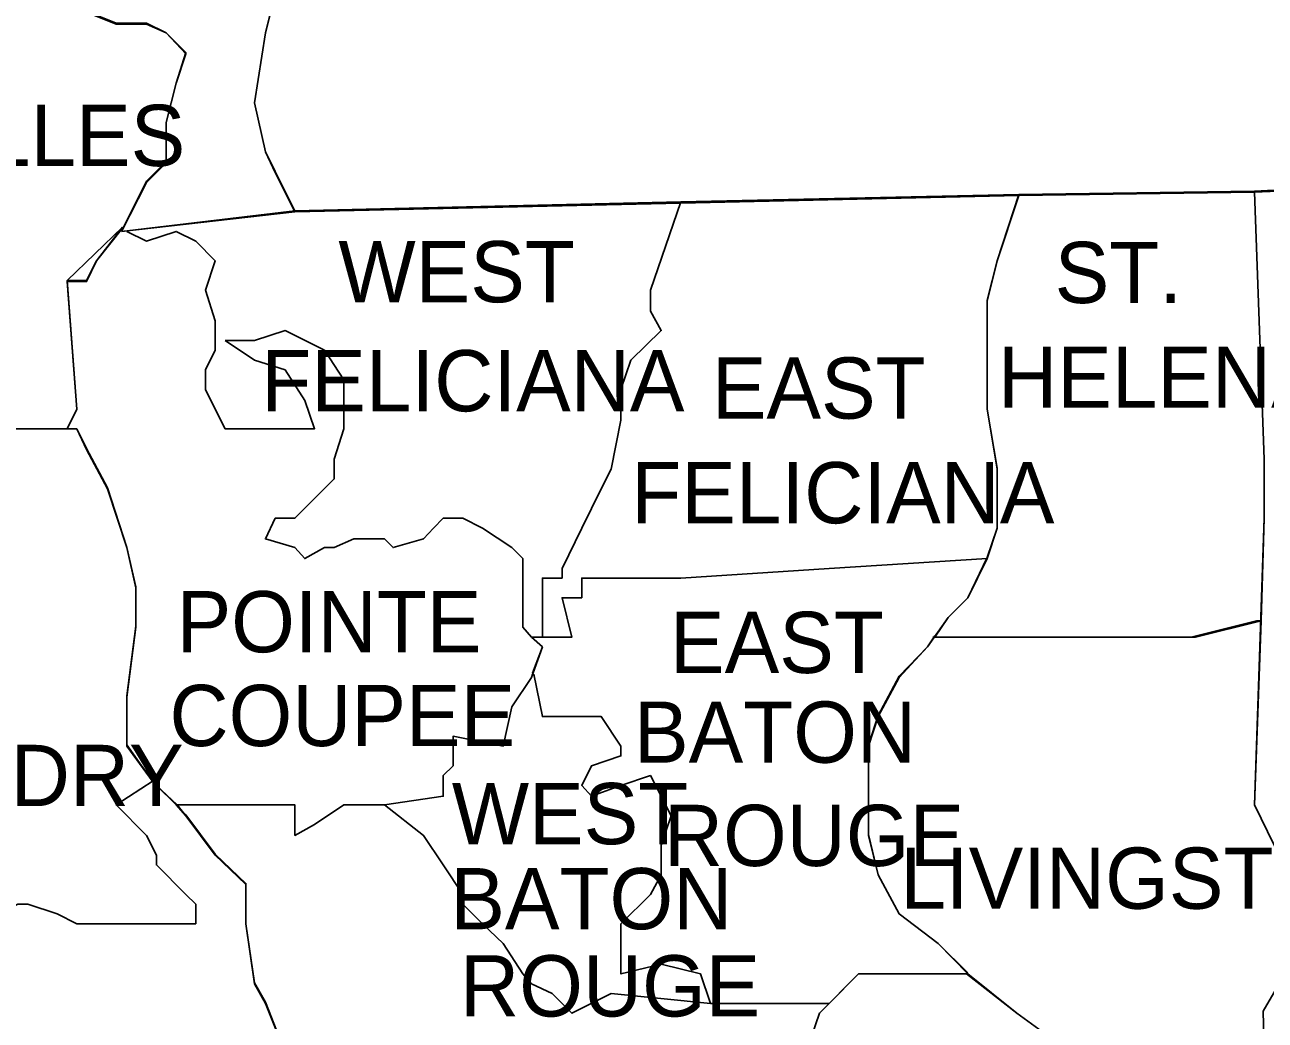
# Model space of a CAD drawing. Extents: x 0.23 to 2.82, y 0.04 to 1.79.
# Drawn here: x 2.3732 to 2.468, y 1.5179 to 1.594 of the extents above; entities that cross this region are included whole.
import ezdxf

# ---------------------------------------------------------------- set-up
doc = ezdxf.new("R2010")
doc.units = 0
for name, color, linetype in [('Dist03', 7, 'Continuous'), ('Dist08', 7, 'Continuous'), ('Dist58', 7, 'Continuous'), ('Dist61', 7, 'Continuous'), ('Dist62', 7, 'Continuous'), ('Standard Info', 7, 'Continuous')]:
    doc.layers.add(name, color=color, linetype=linetype)

msp = doc.modelspace()

# ---------------------------------------------------------------- linework, layer by layer
at = {"layer": 'Dist03'}
for points in [[(2.377154, 1.563083), (2.346904, 1.563083)], [(2.382904, 1.536167), (2.380987, 1.538917), (2.380987, 1.542667), (2.381654, 1.548), (2.381654, 1.551), (2.380987, 1.554), (2.379487, 1.558583), (2.377904, 1.561583), (2.377154, 1.563083)], [(2.409737, 1.49725), (2.408904, 1.499583), (2.407404, 1.501083), (2.403654, 1.501083), (2.402904, 1.502583), (2.402154, 1.505583), (2.40132, 1.508667), (2.40132, 1.510167), (2.400654, 1.511667), (2.39832, 1.512417), (2.39607, 1.512417), (2.39457, 1.513167), (2.39307, 1.515417), (2.39157, 1.51925), (2.390737, 1.52075), (2.39007, 1.52525), (2.39007, 1.528333), (2.387737, 1.530583), (2.385487, 1.533583), (2.384737, 1.534333)]]:
    msp.add_lwpolyline(points, dxfattribs=at)
at = {"layer": 'Dist08'}
for points in [[(2.38057, 1.578167), (2.382487, 1.582), (2.383987, 1.5835), (2.383987, 1.5865), (2.384737, 1.5895), (2.385487, 1.591833), (2.383987, 1.593333), (2.382487, 1.594083), (2.380154, 1.594083), (2.376404, 1.595583), (2.374154, 1.597833), (2.373487, 1.59875)], [(2.376404, 1.574417), (2.377904, 1.574417), (2.378654, 1.575917), (2.380654, 1.5785)], [(2.376404, 1.563083), (2.377154, 1.564583), (2.376404, 1.574417)], [(2.342404, 1.572917), (2.342404, 1.570667), (2.343904, 1.569167), (2.345404, 1.567583), (2.345404, 1.563083), (2.376404, 1.563083)]]:
    msp.add_lwpolyline(points, dxfattribs=at)
at = {"layer": 'Dist58'}
for points in [[(2.40882, 1.639417), (2.406654, 1.635667), (2.405154, 1.631917), (2.405154, 1.628083), (2.402154, 1.625083), (2.39982, 1.620583), (2.39982, 1.613), (2.39907, 1.61), (2.39757, 1.606917), (2.39682, 1.604667), (2.39457, 1.600917), (2.39307, 1.599417), (2.39157, 1.593333), (2.390737, 1.588), (2.39157, 1.58425), (2.39232, 1.58275), (2.39382, 1.57975)], [(2.38057, 1.578167), (2.382487, 1.582), (2.383987, 1.5835), (2.383987, 1.5865), (2.384737, 1.5895), (2.385487, 1.591833), (2.383987, 1.593333), (2.382487, 1.594083), (2.380154, 1.594083), (2.376404, 1.595583), (2.374154, 1.597833), (2.373487, 1.59875)], [(2.39382, 1.57975), (2.38057, 1.578167)]]:
    msp.add_lwpolyline(points, dxfattribs=at)
at = {"layer": 'Dist61'}
msp.add_line((2.376404, 1.574417), (2.380654, 1.5785), dxfattribs=at)
for points in [[(2.42332, 1.580417), (2.39382, 1.57975)], [(2.449154, 1.581), (2.42332, 1.580417)], [(2.446737, 1.55325), (2.447487, 1.5555), (2.447487, 1.560083), (2.446737, 1.564583), (2.446737, 1.569833), (2.446737, 1.572917), (2.447487, 1.575917), (2.449154, 1.581)], [(2.39382, 1.57975), (2.38057, 1.578167)], [(2.380654, 1.5785), (2.378654, 1.575917), (2.377904, 1.574417), (2.376404, 1.574417)], [(2.380487, 1.57825), (2.378654, 1.575917), (2.377904, 1.574417), (2.376404, 1.574417)], [(2.376404, 1.574417), (2.377154, 1.564583), (2.376404, 1.563083)], [(2.377154, 1.563083), (2.377904, 1.561583), (2.379487, 1.558583), (2.380987, 1.554), (2.381654, 1.551), (2.381654, 1.548), (2.380987, 1.542667), (2.380987, 1.538917), (2.382904, 1.536167)], [(2.445237, 1.5215), (2.442987, 1.52375), (2.439987, 1.526), (2.438404, 1.529), (2.437654, 1.532083), (2.437654, 1.535083), (2.437654, 1.538917), (2.438404, 1.541167), (2.439987, 1.544167), (2.442154, 1.546417), (2.443737, 1.548667), (2.445237, 1.550167), (2.446737, 1.55325)], [(2.382987, 1.536167), (2.383237, 1.535833), (2.38482, 1.534333)], [(2.384737, 1.534333), (2.385487, 1.533583), (2.387737, 1.530583), (2.39007, 1.528333), (2.39007, 1.52525), (2.390737, 1.52075), (2.39157, 1.51925), (2.39307, 1.515417), (2.39457, 1.513167), (2.39607, 1.512417), (2.39832, 1.512417), (2.400654, 1.511667), (2.40132, 1.510167), (2.40132, 1.508667), (2.402154, 1.505583), (2.402904, 1.502583), (2.403654, 1.501083), (2.407404, 1.501083), (2.408904, 1.499583), (2.409737, 1.49725)], [(2.463404, 1.506333), (2.463404, 1.511667), (2.462654, 1.512417), (2.461154, 1.510917), (2.45957, 1.507833), (2.45882, 1.508667), (2.45732, 1.510167), (2.45582, 1.512417), (2.45207, 1.516167), (2.448987, 1.518417), (2.445154, 1.5215)]]:
    msp.add_lwpolyline(points, dxfattribs=at)
at = {"layer": 'Dist62'}
for p, q in [((2.449154, 1.581), (2.467154, 1.58125)), ((2.467154, 1.58125), (2.48307, 1.582))]:
    msp.add_line(p, q, dxfattribs=at)
for points in [[(2.446737, 1.55325), (2.447487, 1.5555), (2.447487, 1.560083), (2.446737, 1.564583), (2.446737, 1.569833), (2.446737, 1.572917), (2.447487, 1.575917), (2.449154, 1.581)], [(2.445237, 1.5215), (2.442987, 1.52375), (2.439987, 1.526), (2.438404, 1.529), (2.437654, 1.532083), (2.437654, 1.535083), (2.437654, 1.538917), (2.438404, 1.541167), (2.439987, 1.544167), (2.442154, 1.546417), (2.443737, 1.548667), (2.445237, 1.550167), (2.446737, 1.55325)], [(2.463404, 1.506333), (2.463404, 1.511667), (2.462654, 1.512417), (2.461154, 1.510917), (2.45957, 1.507833), (2.45882, 1.508667), (2.45732, 1.510167), (2.45582, 1.512417), (2.45207, 1.516167), (2.448987, 1.518417), (2.445154, 1.5215)]]:
    msp.add_lwpolyline(points, dxfattribs=at)
at = {"layer": 'Standard Info'}
for p, q in [((2.467154, 1.581167), (2.48307, 1.581917)), ((2.42332, 1.580417), (2.42332, 1.580333)), ((2.449154, 1.580917), (2.467154, 1.581167)), ((2.377154, 1.563083), (2.376404, 1.563083)), ((2.467654, 1.548417), (2.46732, 1.548417)), ((2.38482, 1.534333), (2.384737, 1.534333))]:
    msp.add_line(p, q, dxfattribs=at)
for points in [[(2.40882, 1.639417), (2.406654, 1.635667), (2.405154, 1.631833), (2.405154, 1.628083), (2.402154, 1.625083), (2.39982, 1.6205), (2.39982, 1.612917), (2.39907, 1.609917), (2.39757, 1.606917), (2.39682, 1.604583), (2.39457, 1.600833), (2.39307, 1.599333), (2.39157, 1.593333), (2.390737, 1.588), (2.39157, 1.58425), (2.39232, 1.582667), (2.39382, 1.579667)], [(2.358154, 1.605), (2.35982, 1.603917), (2.36132, 1.601583), (2.36207, 1.600083), (2.36357, 1.598583), (2.36432, 1.597083), (2.36582, 1.596333), (2.36732, 1.597833), (2.36657, 1.599333), (2.36807, 1.600833), (2.371904, 1.600833), (2.374154, 1.597833), (2.376404, 1.5955), (2.380154, 1.594), (2.382487, 1.594), (2.383987, 1.593333), (2.385487, 1.59175), (2.384737, 1.5895), (2.383987, 1.5865), (2.383987, 1.583417), (2.382487, 1.581917), (2.380654, 1.578333)], [(2.38057, 1.578167), (2.382487, 1.581917), (2.383987, 1.583417), (2.383987, 1.5865), (2.384737, 1.5895), (2.385487, 1.59175), (2.383987, 1.593333), (2.382487, 1.594), (2.380154, 1.594), (2.376404, 1.5955), (2.374154, 1.597833), (2.373487, 1.598667)], [(2.39382, 1.579667), (2.42332, 1.580333)], [(2.42332, 1.580417), (2.420987, 1.573667), (2.420987, 1.572083), (2.42182, 1.570583), (2.419487, 1.568333), (2.418737, 1.566083), (2.418737, 1.56375), (2.417987, 1.56), (2.417237, 1.5585), (2.415737, 1.5555), (2.414237, 1.552417), (2.414237, 1.551667), (2.412737, 1.551667), (2.412737, 1.549417), (2.412737, 1.547167)], [(2.412737, 1.547167), (2.412737, 1.549417), (2.412737, 1.551667), (2.414237, 1.551667), (2.414237, 1.552417), (2.415737, 1.5555), (2.417237, 1.5585), (2.417987, 1.56), (2.418737, 1.56375), (2.418737, 1.566083), (2.419487, 1.568333), (2.42182, 1.570583), (2.420987, 1.572083), (2.420987, 1.573667), (2.42332, 1.580417)], [(2.42332, 1.580333), (2.449154, 1.580917)], [(2.449154, 1.580917), (2.447487, 1.575917), (2.446737, 1.572833), (2.446737, 1.569833), (2.446737, 1.564583), (2.447487, 1.56), (2.447487, 1.5555), (2.446737, 1.553167)], [(2.446737, 1.553167), (2.447487, 1.5555), (2.447487, 1.56), (2.446737, 1.564583), (2.446737, 1.569833), (2.446737, 1.572833), (2.447487, 1.575917), (2.449154, 1.580917)], [(2.467154, 1.581167), (2.467904, 1.56075), (2.467904, 1.55625), (2.467654, 1.548417)], [(2.473237, 1.524417), (2.473237, 1.524417), (2.471737, 1.52675), (2.470237, 1.529), (2.468654, 1.53125), (2.467154, 1.534333), (2.467904, 1.55625), (2.467904, 1.56075), (2.467154, 1.581167)], [(2.39382, 1.579667), (2.38057, 1.578167)], [(2.38057, 1.578167), (2.39382, 1.579667)], [(2.380654, 1.578417), (2.378654, 1.575917), (2.377904, 1.574333), (2.376404, 1.574333)], [(2.376404, 1.574333), (2.377904, 1.574333), (2.378654, 1.575917), (2.380487, 1.57825)], [(2.387737, 1.571333), (2.386987, 1.573667), (2.387737, 1.575917), (2.386237, 1.577417), (2.384737, 1.578167), (2.382487, 1.577417), (2.380987, 1.578167)], [(2.380987, 1.578167), (2.382487, 1.577417), (2.384737, 1.578167), (2.386237, 1.577417), (2.387737, 1.575917), (2.386987, 1.573667), (2.387737, 1.571333)], [(2.376404, 1.574333), (2.377154, 1.564583), (2.376404, 1.563083)], [(2.376404, 1.563083), (2.377154, 1.564583), (2.376404, 1.574333)], [(2.376404, 1.563083), (2.345404, 1.563083), (2.345404, 1.567583), (2.343904, 1.569083), (2.342404, 1.570583), (2.342404, 1.572833)], [(2.388487, 1.569833), (2.390737, 1.568333), (2.39307, 1.567583), (2.39457, 1.56525), (2.39532, 1.563083), (2.39382, 1.563083), (2.39007, 1.563083), (2.388487, 1.563083), (2.387737, 1.564583), (2.386987, 1.566083), (2.386987, 1.567583), (2.387737, 1.569083), (2.387737, 1.571333)], [(2.387737, 1.571333), (2.387737, 1.569083), (2.386987, 1.567583), (2.386987, 1.566083), (2.387737, 1.564583), (2.388487, 1.563083), (2.39007, 1.563083), (2.39382, 1.563083), (2.39532, 1.563083), (2.39457, 1.56525), (2.39307, 1.567583), (2.390737, 1.568333), (2.388487, 1.569833)], [(2.411904, 1.547167), (2.411237, 1.547917), (2.411237, 1.550167), (2.411237, 1.553167), (2.410404, 1.554), (2.408154, 1.5555), (2.406654, 1.55625), (2.405154, 1.55625), (2.404404, 1.5555), (2.403654, 1.554667), (2.40132, 1.554), (2.400654, 1.554667), (2.39832, 1.554667), (2.39682, 1.554), (2.39607, 1.554), (2.39457, 1.553167), (2.39382, 1.554), (2.39157, 1.554667), (2.39232, 1.55625), (2.39382, 1.55625), (2.39532, 1.55775), (2.39682, 1.55925), (2.39682, 1.56075), (2.39757, 1.563083), (2.39757, 1.566833), (2.39607, 1.569083), (2.39307, 1.570583), (2.390737, 1.569833), (2.388487, 1.569833)], [(2.388487, 1.569833), (2.390737, 1.569833), (2.39307, 1.570583), (2.39607, 1.569083), (2.39757, 1.566833), (2.39757, 1.563083), (2.39682, 1.56075), (2.39682, 1.55925), (2.39532, 1.55775), (2.39382, 1.55625), (2.39232, 1.55625), (2.39157, 1.554667), (2.39382, 1.554), (2.39457, 1.553167), (2.39607, 1.554), (2.39682, 1.554), (2.39832, 1.554667), (2.400654, 1.554667), (2.40132, 1.554), (2.403654, 1.554667), (2.404404, 1.5555), (2.405154, 1.55625), (2.406654, 1.55625), (2.408154, 1.5555), (2.410404, 1.554), (2.411237, 1.553167), (2.411237, 1.550167), (2.411237, 1.547917), (2.411904, 1.547167), (2.412737, 1.546417), (2.411904, 1.544083), (2.410404, 1.541833), (2.409737, 1.538833), (2.405904, 1.539583), (2.405904, 1.537333), (2.405154, 1.536583), (2.405154, 1.535), (2.400654, 1.534333)], [(2.346904, 1.563083), (2.377154, 1.563083)], [(2.377154, 1.563083), (2.377904, 1.5615), (2.379487, 1.5585), (2.380987, 1.554), (2.381654, 1.550917), (2.381654, 1.547917), (2.380987, 1.542583), (2.380987, 1.538833), (2.382904, 1.536167)], [(2.384737, 1.534333), (2.383237, 1.535833), (2.380987, 1.538833), (2.380987, 1.542583), (2.381654, 1.547917), (2.381654, 1.550917), (2.380987, 1.554), (2.379487, 1.5585), (2.377904, 1.5615), (2.377154, 1.563083)], [(2.411904, 1.547167), (2.414987, 1.547167), (2.414237, 1.550167), (2.415737, 1.550167), (2.415737, 1.551667), (2.42332, 1.551667), (2.434654, 1.552417), (2.446737, 1.553167)], [(2.446737, 1.553167), (2.434654, 1.552417), (2.42332, 1.551667), (2.415737, 1.551667), (2.415737, 1.550167), (2.414237, 1.550167), (2.414987, 1.547167), (2.412737, 1.547167)], [(2.446737, 1.553167), (2.445237, 1.550167), (2.443737, 1.548667), (2.442154, 1.546417), (2.439987, 1.544083), (2.438404, 1.541083), (2.437654, 1.538833), (2.437654, 1.535), (2.437654, 1.532), (2.438404, 1.529), (2.439987, 1.526), (2.442987, 1.52375), (2.445237, 1.521417)], [(2.442737, 1.547167), (2.443737, 1.548667), (2.445237, 1.550167), (2.446737, 1.553167)], [(2.46732, 1.548417), (2.46232, 1.547167), (2.44257, 1.547167)], [(2.442904, 1.547167), (2.462654, 1.547167), (2.467654, 1.548417)], [(2.442904, 1.547167), (2.462654, 1.547167), (2.467654, 1.548417)], [(2.467654, 1.548417), (2.467154, 1.534333), (2.468654, 1.53125), (2.470237, 1.529), (2.471737, 1.52675), (2.473237, 1.524417)], [(2.412737, 1.547167), (2.411904, 1.547167)], [(2.411987, 1.544417), (2.412737, 1.546417), (2.411904, 1.547167)], [(2.462654, 1.512333), (2.461154, 1.510833), (2.45957, 1.507833), (2.45882, 1.508583), (2.45732, 1.510083), (2.45582, 1.512333), (2.45207, 1.516167), (2.448987, 1.518417), (2.445237, 1.521417), (2.442987, 1.52375), (2.439987, 1.526), (2.438404, 1.529), (2.437654, 1.532), (2.437654, 1.535), (2.437654, 1.538833), (2.438404, 1.541083), (2.439987, 1.544083), (2.442154, 1.546417), (2.442737, 1.54725)], [(2.400654, 1.534333), (2.405154, 1.535), (2.405154, 1.536583), (2.405904, 1.537333), (2.405904, 1.539583), (2.409737, 1.538833), (2.410404, 1.541833), (2.411904, 1.544083), (2.411987, 1.544333)], [(2.41207, 1.544333), (2.412737, 1.541083), (2.417237, 1.541083), (2.418737, 1.538833), (2.418737, 1.538083), (2.416487, 1.537333), (2.415737, 1.535833), (2.416487, 1.535), (2.418737, 1.535833), (2.420987, 1.536583), (2.42182, 1.535), (2.42257, 1.5335), (2.42182, 1.53125), (2.42182, 1.529), (2.420987, 1.5275), (2.418737, 1.52525), (2.418737, 1.524417), (2.418737, 1.522917), (2.418737, 1.521417), (2.42182, 1.522167), (2.42482, 1.521417), (2.42557, 1.519167)], [(2.42557, 1.519167), (2.42482, 1.521417), (2.42182, 1.522167), (2.418737, 1.521417), (2.418737, 1.522917), (2.418737, 1.524417), (2.418737, 1.52525), (2.420987, 1.5275), (2.42182, 1.529), (2.42182, 1.53125), (2.42257, 1.5335), (2.42182, 1.535), (2.420987, 1.536583), (2.418737, 1.535833), (2.416487, 1.535), (2.415737, 1.535833), (2.416487, 1.537333), (2.418737, 1.538083), (2.418737, 1.538833), (2.417237, 1.541083), (2.412737, 1.541083), (2.41207, 1.544333)], [(2.36257, 1.523167), (2.36357, 1.52525), (2.36507, 1.526), (2.36657, 1.52525), (2.36807, 1.524417), (2.37107, 1.526), (2.372654, 1.52675), (2.373404, 1.52675), (2.375654, 1.526), (2.377154, 1.52525), (2.386237, 1.52525), (2.386237, 1.52675), (2.385487, 1.5275), (2.383237, 1.52975), (2.383237, 1.5305), (2.382487, 1.532), (2.380154, 1.534333), (2.382987, 1.536167)], [(2.382987, 1.536167), (2.380154, 1.534333), (2.382487, 1.532), (2.383237, 1.5305), (2.383237, 1.52975), (2.385487, 1.5275), (2.386237, 1.52675), (2.386237, 1.52525), (2.377154, 1.52525), (2.375654, 1.526), (2.373404, 1.52675), (2.372654, 1.52675)], [(2.382987, 1.536167), (2.383237, 1.535833), (2.38482, 1.534333)], [(2.384737, 1.534333), (2.385487, 1.5335), (2.387737, 1.5305), (2.39007, 1.52825), (2.39007, 1.52525), (2.390737, 1.520667), (2.39157, 1.519167), (2.39307, 1.515417), (2.39457, 1.513167), (2.39607, 1.512333), (2.39832, 1.512333), (2.400654, 1.511583), (2.40132, 1.510083), (2.40132, 1.508583), (2.402154, 1.505583), (2.402904, 1.502583), (2.403654, 1.501), (2.407404, 1.501), (2.408904, 1.4995), (2.409737, 1.49725)], [(2.400654, 1.534333), (2.39757, 1.534333), (2.39532, 1.532833), (2.39382, 1.532), (2.39382, 1.534333), (2.384737, 1.534333)], [(2.400654, 1.534333), (2.39757, 1.534333), (2.39532, 1.532833), (2.39382, 1.532), (2.39382, 1.534333), (2.384737, 1.534333)], [(2.384737, 1.534333), (2.39382, 1.534333), (2.39382, 1.532), (2.39532, 1.532833), (2.39757, 1.534333), (2.400654, 1.534333)], [(2.418404, 1.493333), (2.419487, 1.495), (2.417987, 1.495), (2.416487, 1.49725), (2.409737, 1.49725), (2.408904, 1.4995), (2.407404, 1.501), (2.403654, 1.501), (2.402904, 1.502583), (2.402154, 1.505583), (2.40132, 1.508583), (2.40132, 1.510083), (2.400654, 1.511583), (2.39832, 1.512333), (2.39607, 1.512333), (2.39457, 1.513167), (2.39307, 1.515417), (2.39157, 1.519167), (2.390737, 1.520667), (2.39007, 1.52525), (2.39007, 1.52825), (2.387737, 1.5305), (2.385487, 1.5335), (2.38482, 1.534333)], [(2.400654, 1.534333), (2.403654, 1.532), (2.405154, 1.52975), (2.406654, 1.5275), (2.406654, 1.52675), (2.408154, 1.52525), (2.409737, 1.52375), (2.411237, 1.521417), (2.411904, 1.520667), (2.413487, 1.519917), (2.414987, 1.518417), (2.417987, 1.519917), (2.42557, 1.519167)], [(2.434654, 1.519167), (2.42557, 1.519167), (2.417987, 1.519917), (2.414987, 1.518417), (2.413487, 1.519917), (2.411904, 1.520667), (2.411237, 1.521417), (2.409737, 1.52375), (2.408154, 1.52525), (2.406654, 1.52675), (2.406654, 1.5275), (2.405154, 1.52975), (2.403654, 1.532), (2.400654, 1.534333)], [(2.400654, 1.534333), (2.403654, 1.532), (2.405154, 1.52975), (2.406654, 1.5275), (2.406654, 1.52675), (2.408154, 1.52525), (2.409737, 1.52375), (2.411237, 1.521417), (2.411904, 1.520667), (2.413487, 1.519917), (2.414987, 1.518417), (2.417987, 1.519917), (2.42557, 1.519167), (2.434654, 1.519167)], [(2.473237, 1.524417), (2.470904, 1.522583), (2.468987, 1.520583), (2.46782, 1.518583), (2.467904, 1.5155), (2.468654, 1.5155), (2.468654, 1.513917), (2.466404, 1.513833), (2.462654, 1.512333)], [(2.42857, 1.49725), (2.42857, 1.4995), (2.42857, 1.501), (2.43007, 1.502583), (2.43007, 1.504083), (2.430904, 1.505583), (2.43157, 1.511583), (2.433904, 1.518417), (2.436904, 1.521417), (2.445237, 1.521417)], [(2.445237, 1.521417), (2.436904, 1.521417), (2.434654, 1.519167)], [(2.445154, 1.521417), (2.448987, 1.518417), (2.45207, 1.516167), (2.45582, 1.512333), (2.45732, 1.510083), (2.45882, 1.508583), (2.45957, 1.507833), (2.461154, 1.510833), (2.462654, 1.512333), (2.463404, 1.511583), (2.463404, 1.506333)], [(2.434654, 1.519167), (2.42557, 1.519167)], [(2.434654, 1.519167), (2.433904, 1.518417), (2.43157, 1.511583), (2.430904, 1.505583), (2.43007, 1.504083), (2.43007, 1.502583), (2.42857, 1.501), (2.42857, 1.4995), (2.42857, 1.49725)]]:
    msp.add_lwpolyline(points, dxfattribs=at)

# ---------------------------------------------------------------- texts
for s, height, p in [('AVOYELLES', 0.004679, (2.348575, 1.583167)), ('WEST', 0.004679, (2.397143, 1.57275)), ('ST.', 0.004679, (2.451885, 1.572691)), ('FELICIANA', 0.004679, (2.391255, 1.564417)), ('HELENA', 0.0046785, (2.447559, 1.564691)), ('EAST', 0.004679, (2.425682, 1.563858)), ('FELICIANA', 0.004679, (2.419531, 1.555858)), ('POINTE', 0.0046785, (2.384779, 1.546)), ('EAST', 0.004679, (2.422489, 1.544417)), ('COUPEE', 0.004679, (2.384234, 1.538833)), ('BATON', 0.004679, (2.419736, 1.537561)), ('ST. LANDRY', 0.004679, (2.34846, 1.53425)), ('WEST', 0.004679, (2.40581, 1.531333)), ('ROUGE', 0.004679, (2.422018, 1.529667)), ('LIVINGSTON', 0.004679, (2.440092, 1.526398)), ('BATON', 0.004679, (2.405697, 1.524833)), ('ROUGE', 0.0046785, (2.406445, 1.518167))]:
    msp.add_text(s, height=height, dxfattribs=at).set_placement(p)

doc.saveas('drawing.dxf')
